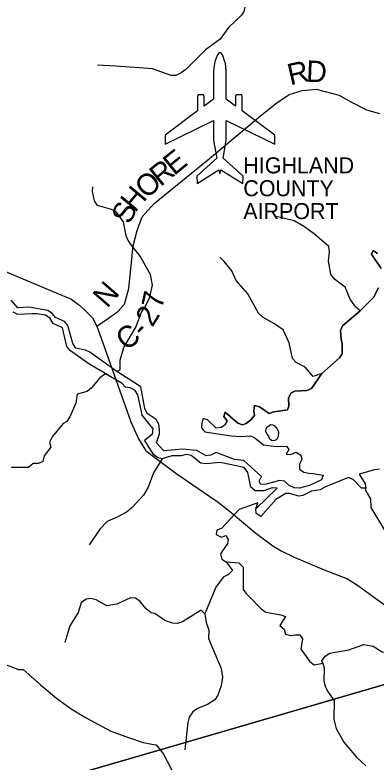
# Model space of a CAD drawing. Extents: x 1525783 to 1900577, y 218250 to 627376.
# Drawn here: x 1671108 to 1676176, y 425388 to 435875 of the extents above; entities that cross this region are included whole.
import ezdxf

# ---------------------------------------------------------------- set-up
doc = ezdxf.new("R2010")
doc.units = 0
for name, color, linetype in [('GM_X_Airport_Class_2', 7, 'Continuous'), ('GM_X_Airport_Location_Class_2', 7, 'Continuous'), ('GM_X_Airport_Text_Class_2', 7, 'Continuous'), ('GM_X_County_Road', 7, 'Continuous'), ('GM_X_County_Road_Text', 7, 'Continuous'), ('GM_X_Major_Lake', 7, 'Continuous'), ('GM_X_Minor_River', 7, 'Continuous'), ('GM_X_State_Route', 7, 'Continuous'), ('GM_X_Township', 7, 'Continuous'), ('GM_X_Township_Road', 7, 'Continuous')]:
    doc.layers.add(name, color=color, linetype=linetype)

msp = doc.modelspace()

# ---------------------------------------------------------------- linework, layer by layer
at = {"layer": 'GM_X_Airport_Class_2'}
msp.add_lwpolyline([(1673671, 434527), (1673215, 434189), (1673215, 434060), (1673894, 434394), (1673894, 434112), (1673939, 433863), (1673660, 433612), (1673664, 433509), (1673970, 433699), (1673984, 433643), (1673998, 433699), (1674304, 433509), (1674309, 433612), (1674029, 433863), (1674074, 434112), (1674074, 434394), (1674753, 434060), (1674753, 434189), (1674297, 434527), (1674297, 434728), (1674290, 434752), (1674212, 434752), (1674205, 434728), (1674205, 434594), (1674074, 434691), (1674074, 434691), (1674074, 435089), (1674061, 435194), (1674050, 435232), (1674023, 435308), (1673998, 435342), (1673984, 435348), (1673970, 435342), (1673945, 435308), (1673918, 435232), (1673907, 435194), (1673894, 435089), (1673894, 434691), (1673763, 434594), (1673763, 434728), (1673756, 434752), (1673678, 434752), (1673671, 434728)], close=True, dxfattribs=at)
at = {"layer": 'GM_X_Airport_Location_Class_2'}
msp.add_line((1673984, 434366), (1673984, 434366), dxfattribs=at)
at = {"layer": 'GM_X_County_Road'}
msp.add_lwpolyline([(1672259, 431507), (1672406, 431610), (1672553, 431714), (1672645, 431816), (1672706, 432033), (1672768, 432636), (1672825, 432849), (1672891, 433039), (1673060, 433229), (1673809, 433837), (1674554, 434458), (1674781, 434640), (1674956, 434758), (1675138, 434813), (1675333, 434835), (1675659, 434750), (1675813, 434660), (1676043, 434541), (1676225, 434493)], dxfattribs=at)
at = {"layer": 'GM_X_Major_Lake'}
for points in [[(1676247, 432316), (1676114, 432516), (1676133, 432570), (1676194, 432527)], [(1676194, 432527), (1676133, 432570), (1676114, 432516), (1676247, 432316)], [(1674053, 430115), (1674088, 430177), (1674041, 430238), (1674056, 430301), (1674235, 430144), (1674301, 430123), (1674355, 430138), (1674420, 430191), (1674470, 430252), (1674459, 430319), (1674470, 430391), (1674540, 430373), (1674676, 430279), (1674743, 430306), (1674932, 430331), (1674950, 430383), (1674949, 430497), (1674982, 430564), (1675036, 430596), (1675205, 430603), (1675269, 430632), (1675415, 430842), (1675662, 431064), (1675699, 431120), (1675699, 431258), (1675688, 431323), (1675678, 431445), (1675704, 431509), (1675952, 431721), (1676139, 431910), (1676210, 432044)], [(1676210, 432044), (1676139, 431910), (1675952, 431721), (1675704, 431509), (1675678, 431445), (1675688, 431323), (1675699, 431258), (1675699, 431120), (1675662, 431064), (1675415, 430842), (1675269, 430632), (1675205, 430603), (1675036, 430596), (1674982, 430564), (1674949, 430497), (1674950, 430383), (1674932, 430331), (1674743, 430306), (1674676, 430279), (1674540, 430373), (1674470, 430391), (1674459, 430319), (1674470, 430252), (1674420, 430191), (1674355, 430138), (1674301, 430123), (1674235, 430144), (1674056, 430301), (1674041, 430238), (1674088, 430177), (1674053, 430115)], [(1674053, 430115), (1674002, 430086), (1673932, 430075), (1673812, 430191), (1673750, 430212), (1673729, 430151), (1673726, 430080), (1673771, 430022), (1674140, 429967), (1674278, 429957), (1674414, 429967), (1674476, 429941), (1674598, 429839), (1674780, 429816), (1674918, 429824), (1674951, 429773), (1674914, 429711), (1674982, 429704), (1675055, 429737), (1675118, 429698), (1675135, 429633), (1675100, 429568), (1675103, 429498), (1675160, 429457), (1675232, 429443), (1675294, 429438), (1675434, 429416), (1675412, 429348), (1675243, 429271), (1675102, 429233), (1675028, 429236), (1674956, 429269), (1674891, 429331), (1674821, 429338), (1674703, 429306), (1674632, 429287), (1674558, 429282), (1674535, 429333), (1674568, 429394), (1674322, 429621), (1674190, 429633), (1673932, 429734), (1673857, 429697), (1673793, 429684), (1673662, 429759), (1673458, 429782), (1673197, 429757), (1673093, 429871), (1673136, 429994), (1673137, 430060), (1673126, 430131), (1673089, 430198), (1672965, 430280), (1672930, 430351), (1672875, 430656), (1672537, 430869), (1672161, 431140), (1672096, 431171), (1671964, 431197), (1671919, 431264), (1671848, 431516), (1671805, 431571), (1671676, 431629), (1671636, 431680), (1671569, 431727), (1671304, 431772), (1671149, 431765), (1671053, 431870)], [(1676222, 429501), (1676156, 429492), (1675940, 429429), (1676022, 429291), (1676033, 429231), (1675971, 429234), (1675857, 429348), (1675787, 429384), (1675456, 429245), (1675390, 429210), (1675271, 429188), (1675146, 429128), (1675094, 429119), (1674960, 429159), (1674908, 429158), (1674771, 429072), (1674558, 428833), (1674495, 428878), (1674488, 428943), (1674788, 429232), (1674720, 429239), (1674599, 429193), (1674477, 429193), (1674419, 429246), (1674388, 429387), (1674377, 429454), (1674324, 429521), (1673989, 429593), (1673785, 429572), (1673715, 429585), (1673581, 429690), (1673513, 429705), (1673442, 429688), (1673308, 429684), (1673173, 429645), (1673111, 429658), (1673058, 429701), (1672924, 429906), (1673039, 429994), (1673049, 430066), (1672892, 430259), (1672877, 430330), (1672831, 430541), (1672788, 430606), (1672725, 430643), (1672659, 430652), (1672614, 430703), (1672144, 430978), (1671887, 431158), (1671834, 431220), (1671775, 431481), (1671642, 431544), (1671603, 431612), (1671536, 431660), (1671418, 431678), (1671348, 431681), (1671148, 431670), (1671084, 431704)], [(1674665, 429962), (1674676, 429934), (1674706, 429905), (1674742, 429901), (1674782, 429916), (1674807, 429964), (1674810, 430018), (1674789, 430072), (1674759, 430101), (1674731, 430118), (1674697, 430120), (1674669, 430105), (1674641, 430087), (1674630, 430067), (1674626, 430039), (1674639, 430005), (1674647, 429985)], [(1674647, 429985), (1674665, 429962)]]:
    msp.add_lwpolyline(points, dxfattribs=at)
at = {"layer": 'GM_X_Minor_River'}
for points in [[(1675715, 437239), (1675757, 437024), (1675506, 436962), (1675211, 436855), (1675022, 436814), (1674949, 436763), (1674792, 436361), (1674739, 436295), (1674608, 436241), (1674433, 436232), (1674374, 436167), (1674346, 436039), (1674320, 435923), (1674287, 435872), (1674105, 435699), (1673988, 435536), (1673781, 435383), (1673506, 435107), (1673441, 435062), (1673367, 435027), (1673300, 435027), (1673040, 435117), (1672524, 435156), (1672266, 435172)], [(1672537, 430869), (1672585, 430892), (1672584, 431028), (1672635, 431206), (1672806, 431494), (1672886, 431703), (1672929, 431774), (1672996, 431900), (1673039, 432081), (1673010, 432232), (1672864, 432491), (1672712, 432684), (1672675, 432757), (1672631, 432971), (1672533, 433107), (1672464, 433142), (1672264, 433201), (1672224, 433264), (1672196, 433397), (1672201, 433461)], [(1675952, 431721), (1675885, 431776), (1675813, 431886), (1675740, 432056), (1675591, 432164), (1675541, 432235), (1675506, 432420), (1675524, 432550), (1675511, 432623), (1675312, 432797), (1675170, 432903), (1675027, 432984), (1674772, 433048)], [(1675415, 430842), (1675292, 430802), (1675181, 430932), (1675056, 430996), (1675003, 431053), (1674957, 431271), (1674874, 431455), (1674751, 431537), (1674593, 431630), (1674526, 431689), (1674378, 431958), (1674212, 432146), (1674152, 432285), (1674044, 432415), (1673985, 432474)], [(1672614, 430703), (1672380, 430837), (1672299, 430783), (1672184, 430642), (1672121, 430591), (1671982, 430551), (1671962, 430427), (1671879, 430234), (1671837, 430169), (1671785, 430140), (1671631, 429952), (1671594, 429878), (1671611, 429808), (1671520, 429685), (1671499, 429607), (1671436, 429578), (1671364, 429577), (1671299, 429524), (1671057, 429522)], [(1673173, 429645), (1673050, 429448), (1672976, 429245), (1672914, 429136), (1672751, 428962), (1672671, 428897), (1672552, 428831), (1672401, 428765), (1672303, 428661), (1672150, 428439)], [(1676033, 429231), (1676024, 429211), (1676096, 429084), (1676104, 428963), (1676292, 428643), (1676358, 428389), (1676401, 427989), (1676456, 427926), (1676525, 427893), (1676772, 427921), (1676846, 427916), (1676987, 427871), (1677057, 427874), (1677128, 427901)], [(1674488, 428943), (1674516, 429028), (1674256, 428932), (1674007, 428668), (1673942, 428641), (1673933, 428583), (1674004, 428546), (1674069, 428567), (1674102, 428512), (1674089, 428458), (1673992, 428309), (1674011, 428237), (1674070, 428198), (1674250, 428184), (1674313, 428123), (1674309, 427810), (1674348, 427758), (1674400, 427707), (1674561, 427539), (1674628, 427490), (1674839, 427454), (1674905, 427429), (1674827, 427306), (1674884, 427253), (1674907, 427181), (1674980, 427165), (1675045, 427174), (1675105, 427173), (1675142, 427116), (1675121, 426974), (1675246, 426798), (1675307, 426753), (1675428, 426775), (1675449, 426712), (1675443, 426522), (1675462, 426453), (1675495, 426384), (1675586, 426248), (1675584, 425992), (1675617, 425857), (1675724, 425668), (1675902, 425455), (1676030, 425336)], [(1674070, 428198), (1674160, 428076), (1674105, 428020), (1674032, 427984), (1673925, 427841), (1673771, 427467), (1673792, 427348), (1673829, 427241), (1673826, 427121), (1674003, 426699), (1674019, 426578), (1674001, 426460), (1673956, 426328), (1673911, 426261), (1673810, 426198), (1673677, 426145), (1673605, 426092), (1673554, 426016), (1673533, 425944), (1673499, 425608), (1673494, 425558)], [(1673771, 427467), (1673719, 427522), (1673458, 427354), (1673390, 427333), (1673320, 427336), (1673210, 427376), (1673072, 427472), (1673018, 427481), (1672951, 427537), (1672867, 427642), (1672800, 427688), (1672730, 427695), (1672536, 427604), (1672399, 427580), (1672247, 427663), (1672175, 427682), (1672107, 427675), (1672038, 427624), (1672014, 427547), (1671993, 427487), (1671880, 427300), (1671807, 427065)], [(1675428, 426775), (1675414, 426811), (1675460, 426874), (1675528, 426917), (1675792, 426961), (1676005, 427036), (1676133, 427013), (1676262, 426935), (1676535, 426910), (1676730, 426817), (1676856, 426728), (1676964, 426594), (1677045, 426404), (1677136, 426268), (1677392, 426095), (1677706, 426002), (1677900, 426006), (1677976, 425957), (1678039, 425896), (1678346, 425640), (1678546, 425514)]]:
    msp.add_lwpolyline(points, dxfattribs=at)
at = {"layer": 'GM_X_State_Route'}
for points in [[(1662968, 436108), (1663385, 435862), (1663817, 435606), (1664181, 435375), (1664409, 435256), (1664430, 435240), (1664529, 435168), (1664692, 435040), (1664784, 434882), (1664846, 434776), (1665020, 434504), (1665084, 434403), (1665251, 434121), (1665347, 433967), (1665439, 433887), (1665467, 433863), (1665649, 433769), (1666995, 433208), (1667677, 432918), (1667825, 432881), (1669547, 432711), (1669864, 432671), (1670122, 432629), (1671775, 431937)], [(1671775, 431937), (1671776, 431937), (1671893, 431888), (1672000, 431810), (1672080, 431742), (1672195, 431622), (1672259, 431507), (1672318, 431340), (1672319, 431338)], [(1672319, 431338), (1672736, 430162), (1672841, 429924), (1672891, 429840), (1672939, 429766), (1673032, 429691), (1673367, 429441), (1673916, 429066)], [(1673916, 429066), (1673917, 429065), (1673939, 429050), (1674112, 428916), (1674488, 428599), (1674728, 428423), (1674845, 428353), (1675025, 428262), (1675447, 428088), (1675774, 427961), (1675916, 427869), (1676634, 427346), (1677405, 426800), (1678767, 425836), (1679011, 425664), (1679618, 425238), (1679799, 425158), (1681504, 424555), (1682911, 423773)]]:
    msp.add_lwpolyline(points, dxfattribs=at)
at = {"layer": 'GM_X_Township'}
for points in [[(1681025, 444291), (1679871, 434929), (1679454, 431544), (1678924, 427242), (1677405, 426800), (1673144, 425561), (1668810, 424300), (1663005, 422598), (1662544, 422468), (1661917, 422302), (1655652, 418075), (1649010, 418793), (1649278, 420121), (1649290, 420273), (1649389, 423628), (1648290, 426895), (1648220, 427103), (1647298, 429844), (1647262, 429928), (1646572, 431971), (1642730, 433950)], [(1647880, 413222), (1648706, 417404), (1649010, 418793), (1655652, 418075), (1661917, 422302), (1662544, 422468), (1663005, 422598), (1668810, 424300), (1673144, 425561), (1677405, 426800), (1678924, 427242), (1678767, 425836), (1677923, 418276), (1678285, 411417)]]:
    msp.add_lwpolyline(points, dxfattribs=at)
at = {"layer": 'GM_X_Township_Road'}
for points in [[(1670731, 426773), (1670783, 426782), (1670881, 426790), (1670983, 426751), (1671089, 426715), (1671155, 426685), (1671221, 426687), (1671465, 426474), (1671693, 426283), (1671897, 426136), (1672099, 426013), (1672455, 425822), (1672703, 425733), (1672909, 425663), (1673079, 425632), (1673081, 425632)], [(1673081, 425632), (1673089, 425630), (1673144, 425561), (1673193, 425498), (1673295, 425303), (1673402, 425076), (1673520, 424945), (1673624, 424875), (1673651, 424462), (1673631, 422703), (1673705, 422655), (1674070, 422618), (1674226, 422589), (1674298, 422511), (1674335, 422340), (1673997, 419705), (1673860, 418777), (1673500, 417430)]]:
    msp.add_lwpolyline(points, dxfattribs=at)

# ---------------------------------------------------------------- texts
at = {"layer": 'GM_X_Airport_Text_Class_2'}
for s, p in [('HIGHLAND', (1674313, 433651)), ('COUNTY', (1674313, 433330)), ('AIRPORT', (1674313, 433009))]:
    msp.add_text(s, height=225, rotation=0, dxfattribs=at).set_placement(p)
at = {"layer": 'GM_X_County_Road_Text'}
for s, rotation, p in [('R', 13.0991, (1674972, 434885)), ('D', 357.7555, (1675191, 434938)), ('E', 39.1564, (1673342, 433612)), ('R', 39.1889, (1673151, 433456)), ('O', 41.0043, (1672954, 433284)), ('H', 49.895, (1672792, 433091)), ('S', 67.1009, (1672726, 432925)), ('N', 49.0834, (1672402, 431749)), ('7', 77.6572, (1673173, 431739)), ('2', 58.6826, (1673037, 431481)), ('C', 35.3476, (1672659, 431153)), ('-', 45.7493, (1672905, 431334))]:
    msp.add_text(s, height=300, rotation=rotation, dxfattribs=at).set_placement(p)

doc.saveas('drawing.dxf')
